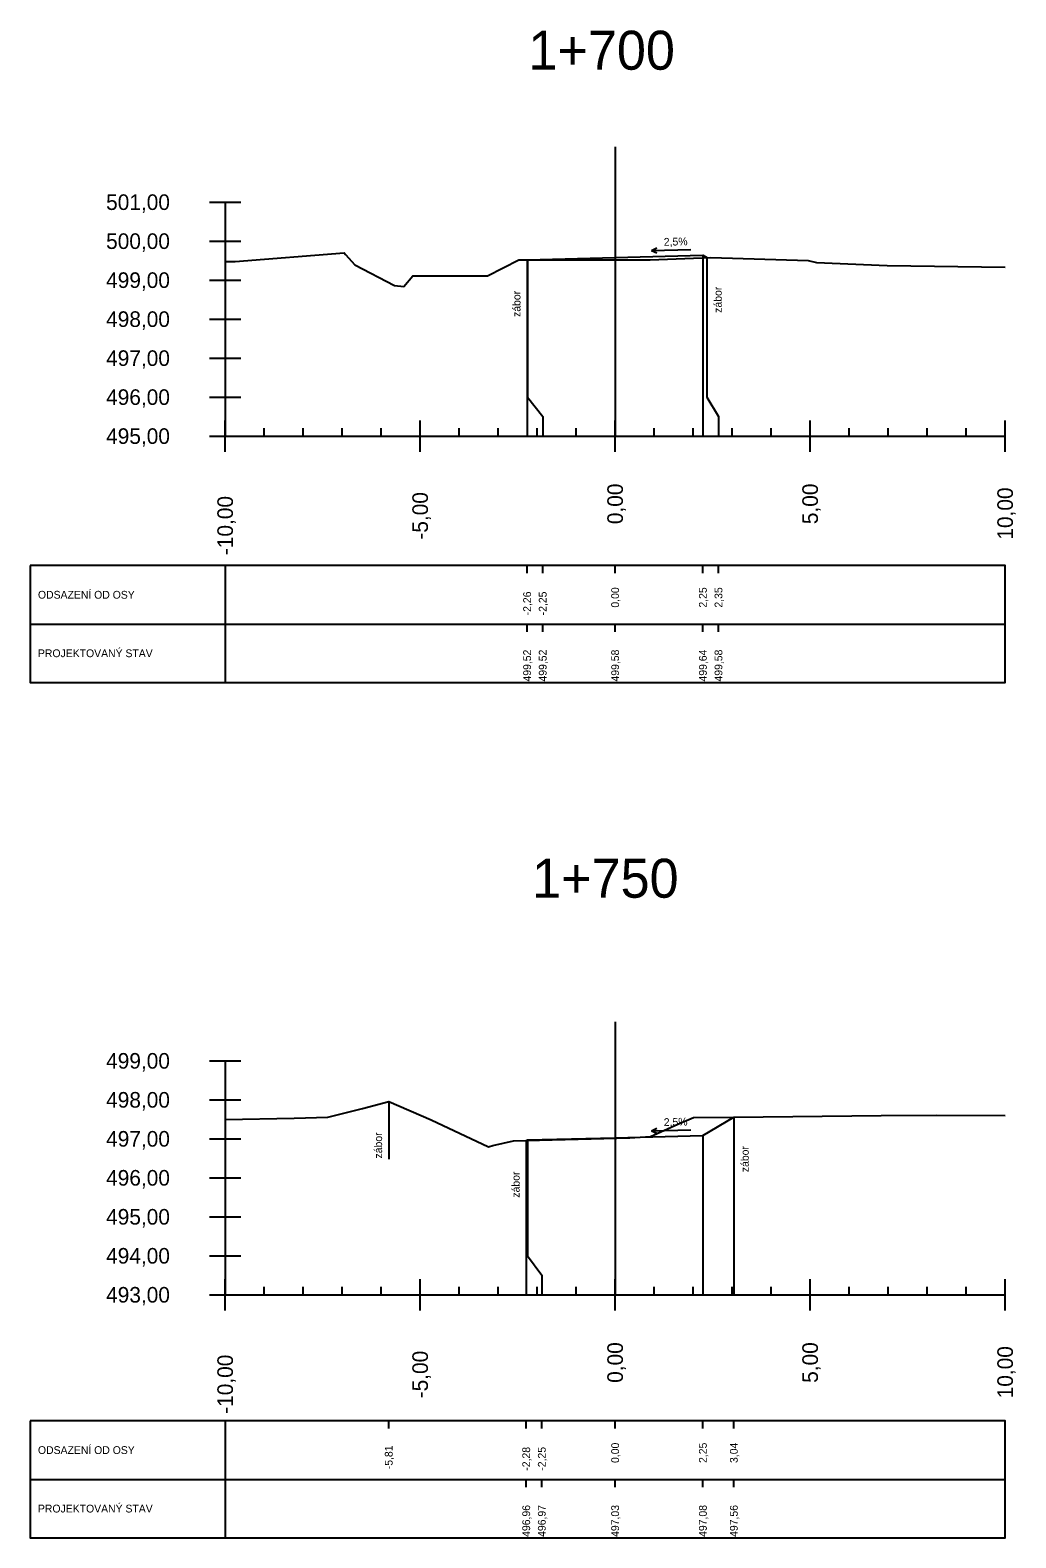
# Model space of a CAD drawing. Extents: x -631407 to -631215, y -1089700 to -1088598.
# Drawn here: x -631285.2 to -631259.93, y -1089190.72 to -1089152.05 of the extents above; entities that cross this region are included whole.
import ezdxf

# ---------------------------------------------------------------- set-up
doc = ezdxf.new("R2010")
doc.units = 0
for name, color, linetype in [('59', 7, 'Continuous'), ('NIVELETA_VYSKY', 7, 'Continuous'), ('REZ_BODY', 7, 'Continuous'), ('REZ_ODSTUPY', 7, 'Continuous'), ('REZ_POPIS', 7, 'Continuous'), ('REZ_RAMY', 7, 'Continuous'), ('REZ_STANICENI', 7, 'Continuous'), ('REZ_SVISLE', 7, 'Continuous'), ('REZ_TENKA', 7, 'Continuous'), ('REZ_TLUSTA', 7, 'Continuous'), ('TABULKA_POPIS', 7, 'Continuous'), ('TEREN', 7, 'Continuous'), ('zábor', 7, 'Continuous')]:
    doc.layers.add(name, color=color, linetype=linetype)

msp = doc.modelspace()

# ---------------------------------------------------------------- linework, layer by layer
at = {"layer": '59'}
for p, q in [((-631280.602, -1089156.464), (-631279.802, -1089156.464)), ((-631280.202, -1089156.464), (-631280.202, -1089162.464)), ((-631280.602, -1089157.464), (-631279.802, -1089157.464)), ((-631280.602, -1089158.464), (-631279.802, -1089158.464)), ((-631280.602, -1089159.464), (-631279.802, -1089159.464)), ((-631280.602, -1089160.464), (-631279.802, -1089160.464)), ((-631280.602, -1089161.464), (-631279.802, -1089161.464)), ((-631280.602, -1089162.464), (-631279.802, -1089162.464)), ((-631280.602, -1089178.486), (-631279.802, -1089178.486)), ((-631280.202, -1089178.486), (-631280.202, -1089184.486)), ((-631280.602, -1089179.486), (-631279.802, -1089179.486)), ((-631280.602, -1089180.486), (-631279.802, -1089180.486)), ((-631280.602, -1089181.486), (-631279.802, -1089181.486)), ((-631280.602, -1089182.486), (-631279.802, -1089182.486)), ((-631280.602, -1089183.486), (-631279.802, -1089183.486)), ((-631280.602, -1089184.486), (-631279.802, -1089184.486))]:
    msp.add_line(p, q, dxfattribs=at)
at = {"layer": 'REZ_RAMY'}
for p, q in [((-631285.202, -1089165.783), (-631285.202, -1089168.783)), ((-631280.202, -1089165.783), (-631280.202, -1089168.783)), ((-631272.459, -1089165.983), (-631272.459, -1089165.783)), ((-631272.059, -1089165.983), (-631272.059, -1089165.783)), ((-631270.202, -1089165.983), (-631270.202, -1089165.783)), ((-631267.952, -1089165.983), (-631267.952, -1089165.783)), ((-631267.552, -1089165.983), (-631267.552, -1089165.783)), ((-631285.202, -1089167.283), (-631260.202, -1089167.283)), ((-631272.459, -1089167.483), (-631272.459, -1089167.283)), ((-631272.059, -1089167.483), (-631272.059, -1089167.283)), ((-631270.202, -1089167.483), (-631270.202, -1089167.283)), ((-631267.952, -1089167.483), (-631267.952, -1089167.283)), ((-631267.552, -1089167.483), (-631267.552, -1089167.283)), ((-631285.202, -1089187.719), (-631285.202, -1089190.719)), ((-631280.202, -1089187.719), (-631280.202, -1089190.719)), ((-631276.007, -1089187.919), (-631276.007, -1089187.719)), ((-631272.482, -1089187.919), (-631272.482, -1089187.719)), ((-631272.082, -1089187.919), (-631272.082, -1089187.719)), ((-631270.202, -1089187.919), (-631270.202, -1089187.719)), ((-631267.952, -1089187.919), (-631267.952, -1089187.719)), ((-631267.158, -1089187.919), (-631267.158, -1089187.719)), ((-631285.202, -1089189.219), (-631260.202, -1089189.219)), ((-631272.482, -1089189.419), (-631272.482, -1089189.219)), ((-631272.082, -1089189.419), (-631272.082, -1089189.219)), ((-631270.202, -1089189.419), (-631270.202, -1089189.219)), ((-631267.952, -1089189.419), (-631267.952, -1089189.219)), ((-631267.158, -1089189.419), (-631267.158, -1089189.219))]:
    msp.add_line(p, q, dxfattribs=at)
for points in [[(-631285.202, -1089165.783), (-631285.202, -1089168.783), (-631260.202, -1089168.783), (-631260.202, -1089165.783)], [(-631285.202, -1089187.719), (-631285.202, -1089190.719), (-631260.202, -1089190.719), (-631260.202, -1089187.719)]]:
    msp.add_lwpolyline(points, close=True, dxfattribs=at)
at = {"layer": 'REZ_SVISLE'}
for points in [[(-631272.459, -1089157.943), (-631272.459, -1089161.464), (-631272.459, -1089161.964), (-631272.459, -1089162.464)], [(-631272.452, -1089157.94), (-631272.452, -1089161.464), (-631272.059, -1089161.964), (-631272.059, -1089162.464)], [(-631270.202, -1089157.884), (-631270.202, -1089161.464), (-631270.202, -1089161.964), (-631270.202, -1089162.464)], [(-631267.952, -1089157.827), (-631267.952, -1089161.464), (-631267.952, -1089161.964), (-631267.952, -1089162.464)], [(-631267.852, -1089157.887), (-631267.852, -1089161.464), (-631267.552, -1089161.964), (-631267.552, -1089162.464)], [(-631267.158, -1089179.927), (-631267.158, -1089183.486), (-631267.158, -1089183.986), (-631267.158, -1089184.486)], [(-631272.452, -1089180.516), (-631272.452, -1089183.486), (-631272.082, -1089183.986), (-631272.082, -1089184.486)], [(-631270.202, -1089180.459), (-631270.202, -1089183.486), (-631270.202, -1089183.986), (-631270.202, -1089184.486)], [(-631267.952, -1089180.403), (-631267.952, -1089183.486), (-631267.952, -1089183.986), (-631267.952, -1089184.486)], [(-631272.482, -1089180.531), (-631272.482, -1089183.486), (-631272.482, -1089183.986), (-631272.482, -1089184.486)]]:
    msp.add_lwpolyline(points, dxfattribs=at)
at = {"layer": 'REZ_TENKA'}
for p, q in [((-631279.202, -1089162.464), (-631279.202, -1089162.264)), ((-631278.202, -1089162.464), (-631278.202, -1089162.264)), ((-631277.202, -1089162.464), (-631277.202, -1089162.264)), ((-631276.202, -1089162.464), (-631276.202, -1089162.264)), ((-631274.202, -1089162.464), (-631274.202, -1089162.264)), ((-631273.202, -1089162.464), (-631273.202, -1089162.264)), ((-631272.202, -1089162.464), (-631272.202, -1089162.264)), ((-631271.202, -1089162.464), (-631271.202, -1089162.264)), ((-631269.202, -1089162.464), (-631269.202, -1089162.264)), ((-631268.202, -1089162.464), (-631268.202, -1089162.264)), ((-631267.202, -1089162.464), (-631267.202, -1089162.264)), ((-631266.202, -1089162.464), (-631266.202, -1089162.264)), ((-631264.202, -1089162.464), (-631264.202, -1089162.264)), ((-631263.202, -1089162.464), (-631263.202, -1089162.264)), ((-631262.202, -1089162.464), (-631262.202, -1089162.264)), ((-631261.202, -1089162.464), (-631261.202, -1089162.264)), ((-631279.202, -1089184.486), (-631279.202, -1089184.286)), ((-631278.202, -1089184.486), (-631278.202, -1089184.286)), ((-631277.202, -1089184.486), (-631277.202, -1089184.286)), ((-631276.202, -1089184.486), (-631276.202, -1089184.286)), ((-631274.202, -1089184.486), (-631274.202, -1089184.286)), ((-631273.202, -1089184.486), (-631273.202, -1089184.286)), ((-631272.202, -1089184.486), (-631272.202, -1089184.286)), ((-631271.202, -1089184.486), (-631271.202, -1089184.286)), ((-631269.202, -1089184.486), (-631269.202, -1089184.286)), ((-631268.202, -1089184.486), (-631268.202, -1089184.286)), ((-631267.202, -1089184.486), (-631267.202, -1089184.286)), ((-631266.202, -1089184.486), (-631266.202, -1089184.286)), ((-631264.202, -1089184.486), (-631264.202, -1089184.286)), ((-631263.202, -1089184.486), (-631263.202, -1089184.286)), ((-631262.202, -1089184.486), (-631262.202, -1089184.286)), ((-631261.202, -1089184.486), (-631261.202, -1089184.286))]:
    msp.add_line(p, q, dxfattribs=at)
at = {"layer": 'REZ_TLUSTA'}
for p, q in [((-631270.202, -1089155.044), (-631270.202, -1089162.464)), ((-631280.202, -1089162.864), (-631280.202, -1089162.064)), ((-631275.202, -1089162.864), (-631275.202, -1089162.064)), ((-631270.202, -1089162.864), (-631270.202, -1089162.064)), ((-631265.202, -1089162.864), (-631265.202, -1089162.064)), ((-631260.202, -1089162.864), (-631260.202, -1089162.064)), ((-631280.202, -1089162.464), (-631260.202, -1089162.464)), ((-631270.202, -1089177.486), (-631270.202, -1089184.486)), ((-631280.202, -1089184.886), (-631280.202, -1089184.086)), ((-631275.202, -1089184.886), (-631275.202, -1089184.086)), ((-631270.202, -1089184.886), (-631270.202, -1089184.086)), ((-631265.202, -1089184.886), (-631265.202, -1089184.086)), ((-631260.202, -1089184.886), (-631260.202, -1089184.086)), ((-631280.202, -1089184.486), (-631260.202, -1089184.486))]:
    msp.add_line(p, q, dxfattribs=at)
at = {"layer": 'TEREN'}
for points in [[(-631280.202, -1089157.985), (-631279.945, -1089157.986), (-631277.153, -1089157.767), (-631277.115, -1089157.807), (-631276.876, -1089158.072), (-631275.856, -1089158.599), (-631275.62, -1089158.623), (-631275.389, -1089158.355), (-631273.472, -1089158.354), (-631272.67, -1089157.943), (-631269.306, -1089157.944), (-631267.752, -1089157.883), (-631265.254, -1089157.961), (-631265.041, -1089158.011), (-631263.225, -1089158.089), (-631260.202, -1089158.129)], [(-631272.459, -1089157.943), (-631272.452, -1089157.94), (-631270.202, -1089157.884), (-631267.952, -1089157.827), (-631267.852, -1089157.887)], [(-631280.202, -1089179.991), (-631278.433, -1089179.96), (-631277.57, -1089179.933), (-631276.684, -1089179.709), (-631276.007, -1089179.527), (-631274.918, -1089179.996), (-631273.448, -1089180.692), (-631273.341, -1089180.66), (-631272.808, -1089180.539), (-631269.829, -1089180.458), (-631269.299, -1089180.425), (-631268.594, -1089180.113), (-631268.192, -1089179.938), (-631267.155, -1089179.927), (-631263.381, -1089179.892), (-631261.951, -1089179.875), (-631260.202, -1089179.887)], [(-631272.482, -1089180.531), (-631272.452, -1089180.516), (-631270.202, -1089180.459), (-631267.952, -1089180.403), (-631267.158, -1089179.927)]]:
    msp.add_lwpolyline(points, dxfattribs=at)
at = {"layer": 'zábor'}
for p, q in [((-631269.269, -1089157.704), (-631269.132, -1089157.639)), ((-631269.269, -1089157.704), (-631268.261, -1089157.679)), ((-631269.269, -1089157.704), (-631269.129, -1089157.762)), ((-631276.007, -1089179.527), (-631276.007, -1089181.008)), ((-631269.269, -1089180.28), (-631269.132, -1089180.215)), ((-631269.269, -1089180.28), (-631268.261, -1089180.255)), ((-631269.269, -1089180.28), (-631269.129, -1089180.337))]:
    msp.add_line(p, q, dxfattribs=at)

# ---------------------------------------------------------------- texts
at = {"layer": 'NIVELETA_VYSKY'}
for s, p in [('499,52', (-631272.359, -1089168.758)), ('499,52', (-631271.959, -1089168.758)), ('499,58', (-631270.102, -1089168.758)), ('499,64', (-631267.852, -1089168.758)), ('499,58', (-631267.452, -1089168.758)), ('496,96', (-631272.382, -1089190.695)), ('496,97', (-631271.982, -1089190.695)), ('497,03', (-631270.102, -1089190.695)), ('497,08', (-631267.852, -1089190.695)), ('497,56', (-631267.058, -1089190.695))]:
    msp.add_text(s, height=0.2, rotation=90, dxfattribs=at).set_placement(p)
at = {"layer": 'REZ_BODY'}
for s, p in [('-2,26', (-631272.359, -1089167.06)), ('-2,25', (-631271.959, -1089167.06)), ('0,00', (-631270.102, -1089166.862)), ('2,25', (-631267.852, -1089166.862)), ('2,35', (-631267.452, -1089166.862)), ('-5,81', (-631275.907, -1089188.96)), ('-2,28', (-631272.382, -1089188.997)), ('-2,25', (-631271.982, -1089188.997)), ('0,00', (-631270.102, -1089188.799)), ('2,25', (-631267.852, -1089188.799)), ('3,04', (-631267.058, -1089188.799))]:
    msp.add_text(s, height=0.2, rotation=90, dxfattribs=at).set_placement(p)
at = {"layer": 'REZ_ODSTUPY'}
for s, p in [('0,00', (-631270.002, -1089164.722)), ('5,00', (-631265.002, -1089164.722)), ('10,00', (-631260.002, -1089165.119)), ('-10,00', (-631280.002, -1089165.516)), ('-5,00', (-631275.002, -1089165.119)), ('0,00', (-631270.002, -1089186.744)), ('5,00', (-631265.002, -1089186.744)), ('10,00', (-631260.002, -1089187.141)), ('-10,00', (-631280.002, -1089187.538)), ('-5,00', (-631275.002, -1089187.141))]:
    msp.add_text(s, height=0.4, rotation=90, dxfattribs=at).set_placement(p)
at = {"layer": 'REZ_POPIS'}
for s, p in [('501,00', (-631283.254, -1089156.664)), ('500,00', (-631283.254, -1089157.664)), ('499,00', (-631283.254, -1089158.664)), ('498,00', (-631283.254, -1089159.664)), ('497,00', (-631283.254, -1089160.664)), ('496,00', (-631283.254, -1089161.664)), ('495,00', (-631283.254, -1089162.664)), ('499,00', (-631283.254, -1089178.686)), ('498,00', (-631283.254, -1089179.686)), ('497,00', (-631283.254, -1089180.686)), ('496,00', (-631283.254, -1089181.686)), ('495,00', (-631283.254, -1089182.686)), ('494,00', (-631283.254, -1089183.686)), ('493,00', (-631283.254, -1089184.686))]:
    msp.add_text(s, height=0.4, dxfattribs=at).set_placement(p)
at = {"layer": 'REZ_STANICENI'}
for s, p in [('1+700', (-631272.425, -1089153.067)), ('1+750', (-631272.33, -1089174.303))]:
    msp.add_text(s, height=1, dxfattribs=at).set_placement(p)
at = {"layer": 'TABULKA_POPIS'}
for s, p in [('ODSAZENÍ OD OSY', (-631285.002, -1089166.633)), ('PROJEKTOVANÝ STAV', (-631285.002, -1089168.133)), ('ODSAZENÍ OD OSY', (-631285.002, -1089188.569)), ('PROJEKTOVANÝ STAV', (-631285.002, -1089190.069))]:
    msp.add_text(s, height=0.2, dxfattribs=at).set_placement(p)
at = {"layer": 'zábor'}
for s, rotation, p in [('2,5%', 1.4321, (-631268.952, -1089157.583)), ('zábor', 90, (-631272.629, -1089159.407)), ('zábor', 90, (-631267.469, -1089159.301)), ('2,5%', 1.4321, (-631268.952, -1089180.159)), ('zábor', 90, (-631276.177, -1089180.99)), ('zábor', 90, (-631266.776, -1089181.341)), ('zábor', 90, (-631272.652, -1089181.994))]:
    msp.add_text(s, height=0.2, rotation=rotation, dxfattribs=at).set_placement(p)

doc.saveas('drawing.dxf')
